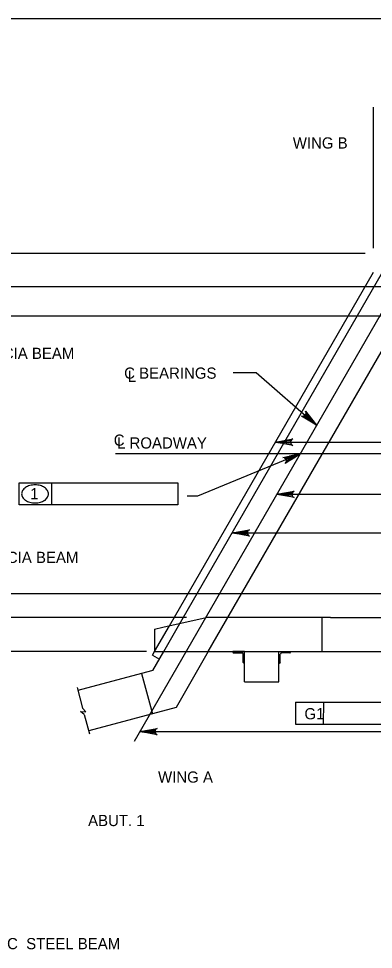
# Model space of a CAD drawing. Extents: x 638175 to 640495, y 294277 to 298435.
# Drawn here: x 638564.5 to 638659.6, y 295201.3 to 295450.5 of the extents above; entities that cross this region are included whole.
import ezdxf

# ---------------------------------------------------------------- set-up
doc = ezdxf.new("R2010")
doc.units = 0
for name, color, linetype in [('2', 7, 'Continuous'), ('3', 7, 'Continuous'), ('4', 7, 'Continuous')]:
    doc.layers.add(name, color=color, linetype=linetype)

msp = doc.modelspace()

# ---------------------------------------------------------------- linework, layer by layer
at = {"layer": '2'}
for p, q in [((638475.46, 295450.46), (639261.46, 295450.46)), ((638615.32, 295281.03), (638676.94, 295387.76)), ((638604.93, 295287.95), (638659.57, 295382.59)), ((638606.97, 295287.25), (638662.02, 295382.59)), ((638603.1, 295287.54), (638614.78, 295290.15)), ((638648.08, 295290.15), (638614.78, 295290.15)), ((638645.81, 295281.03), (638645.81, 295290.15)), ((638648.08, 295290.15), (638790.52, 295290.15)), ((638600.93, 295281.03), (638604.92, 295287.95)), ((638600.93, 295287.06), (638603.1, 295287.54)), ((638600.93, 295287.06), (638600.93, 295281.03)), ((638603.38, 295281.03), (638606.97, 295287.25)), ((638600.93, 295286.19), (638600.93, 295281.03)), ((638600.38, 295280.07), (638600.93, 295281.03)), ((638600.38, 295280.07), (638602.22, 295279.01)), ((638600.47, 295275.98), (638603.38, 295281.03)), ((638600.93, 295281.03), (638804.51, 295281.03)), ((638600.93, 295281.03), (638799.6, 295281.03)), ((638603.38, 295281.03), (638802.05, 295281.03)), ((638615.32, 295281.03), (638606.69, 295266.08)), ((638621.93, 295280.84), (638621.93, 295281.03)), ((638625.02, 295281.03), (638621.93, 295281.03)), ((638622.11, 295280.66), (638624.29, 295280.66)), ((638624.66, 295278.12), (638624.66, 295280.3)), ((638625.02, 295281.03), (638634.26, 295281.03)), ((638625.02, 295272.94), (638625.02, 295281.03)), ((638625.02, 295277.94), (638625.02, 295281.03)), ((638634.26, 295281.03), (638637.35, 295281.03)), ((638634.26, 295272.94), (638634.26, 295281.03)), ((638634.26, 295277.94), (638634.26, 295281.03)), ((638634.62, 295278.12), (638634.62, 295280.3)), ((638637.17, 295280.66), (638634.99, 295280.66)), ((638637.35, 295280.84), (638637.35, 295281.03)), ((638624.84, 295277.94), (638625.02, 295277.94)), ((638634.44, 295277.94), (638634.26, 295277.94)), ((638597.45, 295275.17), (638580.37, 295270.6)), ((638600.47, 295275.98), (638597.45, 295275.17)), ((638597.45, 295275.17), (638600.34, 295264.38)), ((638625.02, 295272.94), (638634.26, 295272.94)), ((638638.68, 295267.51), (638638.67, 295261.6)), ((638638.68, 295267.51), (638665.18, 295267.51)), ((638646.23, 295261.6), (638646.24, 295267.51)), ((638606.69, 295266.08), (638583.26, 295259.8)), ((638638.67, 295261.6), (638665.18, 295261.6))]:
    msp.add_line(p, q, dxfattribs=at)
for centre, radius, start, end in [((638622.11, 295280.84), 0.182, 180.0016, 270), ((638624.29, 295280.3), 0.364, 0.0016, 90), ((638634.99, 295280.3), 0.364, 90, 179.9984), ((638637.17, 295280.84), 0.182, 270, 359.9984), ((638624.84, 295278.12), 0.182, 180.0016, 270), ((638634.44, 295278.12), 0.182, 270, 359.9984)]:
    msp.add_arc(centre, radius, start, end, dxfattribs=at)
at = {"layer": '3'}
for p, q in [((638580.14, 295271.43), (638581.64, 295265.83)), ((638581.04, 295264.95), (638582.53, 295264.86)), ((638582.09, 295264.16), (638581.04, 295264.95)), ((638582.53, 295264.86), (638581.64, 295265.83)), ((638582.09, 295264.16), (638583.47, 295259.04))]:
    msp.add_line(p, q, dxfattribs=at)
at = {"layer": '4'}
for p, q in [((638659.56, 295388.98), (638659.56, 295426.73)), ((638689.46, 295419.78), (638595.44, 295256.93)), ((638657.4, 295387.6), (638485.03, 295387.6)), ((638667.7, 295378.63), (638501.09, 295378.63)), ((638863.78, 295370.8), (638515.73, 295370.8)), ((638622, 295355.74), (638628.13, 295355.74)), ((638628.13, 295355.74), (638644.34, 295341.64)), ((638633.3, 295337.09), (638833.89, 295337.09)), ((638882.76, 295333.98), (638590.47, 295333.98)), ((638639.92, 295333.98), (638612.44, 295322.66)), ((638564.65, 295326.19), (638607.17, 295326.19)), ((638564.65, 295320.28), (638564.65, 295326.19)), ((638573.39, 295320.28), (638573.39, 295326.19)), ((638607.17, 295326.19), (638607.17, 295320.28)), ((638612.44, 295322.66), (638609.61, 295322.66)), ((638633.64, 295323.11), (638817.4, 295323.11)), ((638607.17, 295320.28), (638564.65, 295320.28)), ((638621.72, 295312.78), (638817.4, 295312.78)), ((638825.02, 295296.45), (638515.26, 295296.45)), ((638609.48, 295290.15), (638501.09, 295290.15)), ((638598.75, 295281.03), (638485.03, 295281.03)), ((638596.97, 295259.58), (638780.72, 295259.58)), ((638600.15, 295259.58), (638777.9, 295259.58))]:
    msp.add_line(p, q, dxfattribs=at)
for points in [[(638644.34, 295341.64), (638640.26, 295344.04), (638640.69, 295343.99), (638641.03, 295344.1), (638641.28, 295344.31), (638641.44, 295344.58), (638641.51, 295344.93), (638641.4, 295345.36), (638644.34, 295341.64), (638641.51, 295344.93), (638641.44, 295344.58), (638644.34, 295341.64), (638641.28, 295344.31), (638641.03, 295344.1), (638644.34, 295341.64), (638640.69, 295343.99)], [(638633.3, 295337.09), (638637.96, 295337.96), (638637.6, 295337.71), (638637.41, 295337.4), (638637.36, 295337.09), (638637.41, 295336.77), (638637.6, 295336.46), (638637.96, 295336.21), (638633.3, 295337.09), (638637.6, 295336.46), (638637.41, 295336.77), (638633.3, 295337.09), (638637.36, 295337.09), (638637.41, 295337.4), (638633.3, 295337.09), (638637.6, 295337.71)], [(638639.92, 295333.98), (638635.95, 295331.39), (638636.18, 295331.76), (638636.24, 295332.12), (638636.17, 295332.43), (638636, 295332.7), (638635.71, 295332.92), (638635.28, 295333.01), (638639.92, 295333.98), (638635.71, 295332.92), (638636, 295332.7), (638639.92, 295333.98), (638636.17, 295332.43), (638636.24, 295332.12), (638639.92, 295333.98), (638636.18, 295331.76)], [(638633.64, 295323.11), (638638.31, 295323.98), (638637.95, 295323.73), (638637.76, 295323.42), (638637.71, 295323.11), (638637.76, 295322.79), (638637.95, 295322.48), (638638.31, 295322.23), (638633.64, 295323.11), (638637.95, 295322.48), (638637.76, 295322.79), (638633.64, 295323.11), (638637.71, 295323.11), (638637.76, 295323.42), (638633.64, 295323.11), (638637.95, 295323.73)], [(638621.72, 295312.78), (638626.38, 295313.65), (638626.02, 295313.4), (638625.83, 295313.09), (638625.78, 295312.78), (638625.83, 295312.47), (638626.02, 295312.15), (638626.38, 295311.91), (638621.72, 295312.78), (638626.02, 295312.15), (638625.83, 295312.47), (638621.72, 295312.78), (638625.78, 295312.78), (638625.83, 295313.09), (638621.72, 295312.78), (638626.02, 295313.4)], [(638596.97, 295259.58), (638601.63, 295260.46), (638601.27, 295260.21), (638601.09, 295259.9), (638601.03, 295259.58), (638601.09, 295259.27), (638601.27, 295258.96), (638601.63, 295258.71), (638596.97, 295259.58), (638601.27, 295258.96), (638601.09, 295259.27), (638596.97, 295259.58), (638601.03, 295259.58), (638601.09, 295259.9), (638596.97, 295259.58), (638601.27, 295260.21)]]:
    msp.add_lwpolyline(points, dxfattribs=at)
for points in [[(638641.79, 295343.21), (638642.44, 295343.95), (638644.34, 295341.64)], [(638637.12, 295333.33), (638637.48, 295332.46), (638639.92, 295333.98)], [(638636.6, 295323.6), (638636.6, 295322.61), (638633.64, 295323.11)]]:
    msp.add_lwpolyline(points, close=True, dxfattribs=at)
for centre, radius, start, end in [((638566.97, 295323.22), 1.68, 148.5507, 180), ((638567.89, 295322.67), 2.75, 124.109, 148.5507), ((638568.49, 295321.78), 3.82, 105.6708, 124.109), ((638568.88, 295320.38), 5.27, 90, 105.6708), ((638568.88, 295320.38), 5.27, 74.3292, 90), ((638569.27, 295321.78), 3.82, 55.891, 74.3292), ((638569.87, 295322.67), 2.75, 31.4493, 55.891), ((638570.78, 295323.22), 1.68, 0, 31.4493), ((638566.97, 295323.22), 1.68, 180, 211.4493), ((638567.89, 295323.78), 2.75, 211.4493, 235.891), ((638569.87, 295323.78), 2.75, 304.109, 328.5507), ((638570.78, 295323.22), 1.68, 328.5507, 0), ((638568.49, 295324.67), 3.82, 235.891, 254.3292), ((638568.88, 295326.07), 5.27, 254.3292, 270), ((638568.88, 295326.07), 5.27, 270, 285.6708), ((638569.27, 295324.67), 3.82, 285.6708, 304.109)]:
    msp.add_arc(centre, radius, start, end, dxfattribs=at)

# ---------------------------------------------------------------- texts
at = {"layer": '2'}
msp.add_text('G1', height=3, rotation=359.9382, dxfattribs=at).set_placement((638641.08, 295262.88))
at = {"layer": '4'}
for s, p in [('WING B', (638637.96, 295415.67)), ('L FASCIA BEAM', (638549.09, 295359.35)), ('C BEARINGS', (638592.76, 295354.06)), ('L', (638593.75, 295353.21)), ('C', (638589.98, 295336.12)), ('L ROADWAY', (638590.86, 295335.36)), ('1', (638567.58, 295321.77)), ('L FASCIA BEAM', (638550.18, 295304.73)), ('WING A', (638601.85, 295245.93)), ('ABUT. 1', (638583.1, 295234.3)), ('C  STEEL BEAM', (638561.38, 295201.34))]:
    msp.add_text(s, height=3, dxfattribs=at).set_placement(p)

doc.saveas('drawing.dxf')
